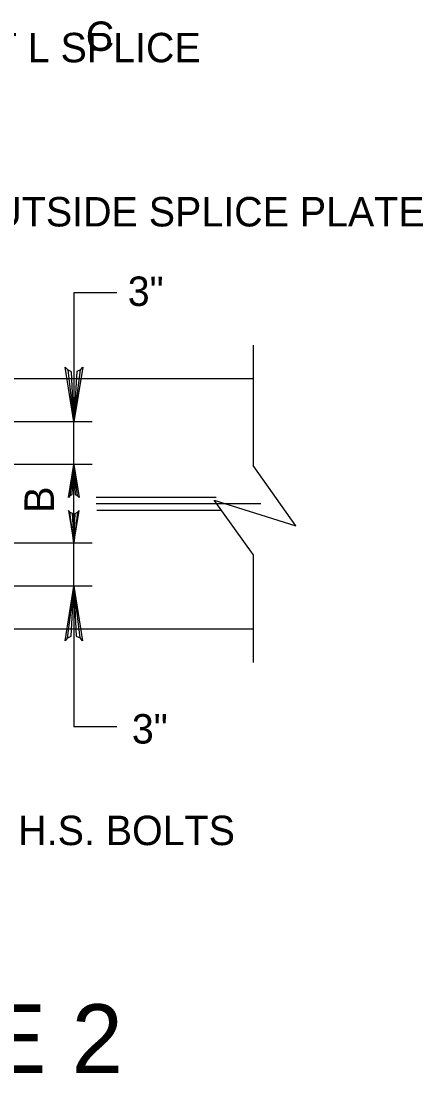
# Model space of a CAD drawing. Extents: x 638466 to 639375, y 297808 to 298996.
# Drawn here: x 639013.8 to 639058, y 298102.1 to 298218 of the extents above; entities that cross this region are included whole.
import ezdxf

# ---------------------------------------------------------------- set-up
doc = ezdxf.new("R2010")
doc.units = 0
for name, color, linetype in [('1', 7, 'Continuous'), ('2', 7, 'Continuous'), ('4', 7, 'Continuous')]:
    doc.layers.add(name, color=color, linetype=linetype)

msp = doc.modelspace()

# ---------------------------------------------------------------- linework, layer by layer
at = {"layer": '1'}
for points in [[(639020.35, 298179.64), (639019.94, 298179.43), (639019.63, 298173.92), (639020.35, 298179.64), (639020.6, 298179.93), (639019.63, 298173.92), (639019.36, 298179.42), (639018.95, 298179.62), (639019.63, 298173.92), (639018.68, 298179.93), (639018.95, 298179.62)], [(639019.2, 298165.76), (639019.45, 298165.89), (639019.63, 298169.2), (639019.2, 298165.76), (639019.05, 298165.58), (639019.63, 298169.2), (639019.79, 298165.9), (639020.04, 298165.77), (639019.63, 298169.2), (639020.2, 298165.58), (639020.04, 298165.77)], [(639019.2, 298163.97), (639019.45, 298163.84), (639019.63, 298160.53), (639019.2, 298163.97), (639019.05, 298164.14), (639019.63, 298160.53), (639019.79, 298163.83), (639020.04, 298163.95), (639019.63, 298160.53), (639020.2, 298164.14), (639020.04, 298163.95)], [(639018.91, 298150.09), (639019.33, 298150.3), (639019.63, 298155.81), (639018.91, 298150.09), (639018.66, 298149.8), (639019.63, 298155.81), (639019.9, 298150.31), (639020.31, 298150.11), (639019.63, 298155.81), (639020.58, 298149.8), (639020.31, 298150.11)]]:
    msp.add_lwpolyline(points, dxfattribs=at)
at = {"layer": '2'}
for p, q in [((639039.34, 298182.34), (639039.34, 298169.09)), ((639039.34, 298178.64), (638969.65, 298178.64)), ((639044.06, 298162.45), (639039.34, 298169.09)), ((639035.29, 298165.57), (639022.07, 298165.57)), ((639040.21, 298164.86), (639022.1, 298164.86)), ((639039.34, 298159.3), (639035.08, 298165.29)), ((639035.08, 298165.29), (639044.06, 298162.45)), ((639035.88, 298164.16), (639022.14, 298164.16)), ((639039.34, 298159.3), (639039.34, 298147.4)), ((639039.34, 298151.08), (638969.65, 298151.08))]:
    msp.add_line(p, q, dxfattribs=at)
at = {"layer": '4'}
for p, q in [((639019.63, 298188.09), (639019.63, 298173.92)), ((639024.34, 298188.09), (639019.63, 298188.09)), ((639021.65, 298173.92), (638993.33, 298173.92)), ((639019.63, 298169.2), (639019.63, 298173.92)), ((639021.65, 298169.2), (638993.33, 298169.2)), ((639019.63, 298155.81), (639019.63, 298169.2)), ((639021.65, 298160.53), (638993.33, 298160.53)), ((639021.65, 298155.81), (638993.33, 298155.81)), ((639019.63, 298155.81), (639019.63, 298140.33)), ((639024.34, 298140.33), (639019.63, 298140.33))]:
    msp.add_line(p, q, dxfattribs=at)

# ---------------------------------------------------------------- texts
for s, height, p in [('C', 3.24, (639020.94, 298214.73)), ('SYM. ABOUT L SPLICE', 3.2401, (638986.63, 298213.48)), ('OUTSIDE SPLICE PLATE', 3.24, (639007.41, 298195.41)), ('3"', 3.24, (639025.56, 298186.66)), ('3"', 3.24, (639026.01, 298138.49)), ('L H.S. BOLTS', 3.2401, (639009.9, 298127.31)), ('FLANGE SPLICE DETAIL - TYPE 2', 7.56, (638863.78, 298102.23))]:
    msp.add_text(s, height=height, dxfattribs=at).set_placement(p)
msp.add_text('B', height=3.24, rotation=90, dxfattribs=at).set_placement((639017.44, 298163.89))

doc.saveas('drawing.dxf')
